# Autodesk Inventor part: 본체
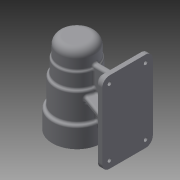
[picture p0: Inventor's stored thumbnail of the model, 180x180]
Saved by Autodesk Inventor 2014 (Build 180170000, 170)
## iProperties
Created: 2016-06
Part Number: 본체
Material: 일반
Document SubType Name: Modeling
Designer: SEC
Density: 1 g/cm^3
Appearance: 기본값
Mass: 247.993 g
Surface Area: 647.07 cm^2
Volume: 247.993 cm^3
Author: SEC
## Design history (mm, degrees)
sketch "스케치1"
  geometry: C1 r 34 at (0, 0); 1 further point
  constraints: 1 centre point, 1 coincident
  dimensions: "d0" = 68 diameter of C1
extrude "돌출1" new body sketch "스케치1" distance "d1" = 28; taper "d2" = 0 deg
sketch "스케치2"
  geometry: C1 r 34 at (0, 0) reference; C2 r 30 at (0, 0)
  constraints: 1 centre point, 1 coincident
  dimensions: "d3" = 60 diameter of C2
extrude "돌출2" join sketch "스케치2" distance "d4" = 39; taper "d5" = 0 deg
sketch "스케치3"
  geometry: C1 r 30 at (0, 0) reference; C2 r 27 at (0, 0)
  constraints: 1 centre point, 1 coincident
  dimensions: "d6" = 54 diameter of C2
extrude "돌출3" join sketch "스케치3" distance "d7" = 20; taper "d8" = 0 deg
sketch "스케치4"
  geometry: C1 r 27 at (0, 0) reference; C2 r 25 at (0, 0)
  constraints: 1 centre point, 1 coincident
  dimensions: "d9" = 50 diameter of C2
extrude "돌출4" join sketch "스케치4" distance "d10" = 25; taper "d11" = 0 deg
sketch "스케치5"
  geometry: L1 (-34, 0)-(-34, 28) reference; L2 (-34, 28)-(-30, 28) reference; L3 (-30, 28)-(-30, 67) reference; L4 (-30, 67)-(-27, 67) reference; L5 (-27, 67)-(-27, 87) reference; L6 (-27, 87)-(-25, 87) reference; L7 (-25, 87)-(-25, 112) reference; L8 (-25, 112)-(25, 112) reference; L9 (25, 112)-(25, 87) reference; L10 (25, 87)-(27, 87) reference; L11 (27, 87)-(27, 67) reference; L12 (27, 67)-(30, 67) reference; L13 (30, 67)-(30, 28) reference; L14 (30, 28)-(34, 28) reference; L15 (34, 28)-(34, 0) reference; L16 (34, 0)-(-34, 0) reference; L17 (-60, 112)-(-70, 112); L18 (-70, 112)-(-70, 0); L19 (-70, 0)-(-60, 0); L20 (-60, 0)-(-60, 112); L21 (0, 112)-(0, 0)
  constraints: 10 end point, 3 parallel, 1 collinear, 1 horizontal, 1 midpoint, 1 perpendicular
  dimensions: "d12" = 70 distance between parallel lines of L18 L21; "d13" = 10 distance between parallel lines of L18 L20; "d14" = 112 distance of L19.end L17.start; "d15" = 0 distance between parallel lines of L19 L16
extrude "돌출5" join sketch "스케치5" stored distance "d16" = 70; taper "d17" = 0 deg
node "작업 평면1"
sketch "스케치6"
  geometry: L1 (70, -35)-(60, -35) reference; L2 (60, -35)-(60, 35) reference; L3 (60, 35)-(70, 35) reference; L4 (70, 35)-(70, -35) reference; L5 (60, -28)-(15, -11.621); L6 (15, -11.621)-(15, 11.621); L7 (15, 11.621)-(60, 28); L8 (60, -28)-(60, 28); C1 r 30 at (0, 0) reference; 1 further point
  constraints: 8 end point, 2 point on line, 1 collinear, 1 parallel
  dimensions: "d18" = 110 deg angle of L2 L7; "d19" = 110 deg angle of L2 L5; "d20" = 7 distance from line of L7.end L3; "d21" = 7 distance from line of L1 L5.start; "d22" = 45 distance between parallel lines of L2 L6
extrude "돌출6" join sketch "스케치6" stored distance "d23" = 8; taper "d24" = 0 deg
node "작업 평면2"
sketch "스케치7"
  geometry: L1 (34, 0)-(34, -28) reference; L2 (34, -28)-(30, -28) reference; L3 (30, -28)-(30, -52) reference; L4 (30, -52)-(60, -52) reference; L5 (60, -52)-(60, 0) reference; L6 (60, 0)-(70, 0) reference; L7 (70, 0)-(70, -112) reference; L8 (70, -112)-(60, -112) reference; L9 (60, -112)-(60, -60) reference; L10 (60, -60)-(30, -60) reference; L11 (30, -60)-(30, -67) reference; L12 (30, -67)-(27, -67) reference; L13 (27, -67)-(27, -87) reference; L14 (27, -87)-(25, -87) reference; L15 (25, -87)-(25, -112) reference; L16 (25, -112)-(-25, -112) reference; L17 (-25, -112)-(-25, -87) reference; L18 (-25, -87)-(-27, -87) reference; L19 (-27, -87)-(-27, -67) reference; L20 (-27, -67)-(-30, -67) reference; L21 (-30, -67)-(-30, -28) reference; L22 (-30, -28)-(-34, -28) reference; L23 (-34, -28)-(-34, 0) reference; L24 (-34, 0)-(34, 0) reference; L25 (60, -92)-(20, -92); L26 (20, -92)-(20, -20); L27 (20, -20)-(60, -20); L28 (60, -20)-(60, -92); L29 (0, -112)-(0, 0)
  constraints: 10 end point, 3 parallel, 1 horizontal, 1 midpoint, 1 perpendicular, 1 point on line
  dimensions: "d25" = 20 distance between parallel lines of L8 L25; "d26" = 20 distance between parallel lines of L27 L6; "d27" = 40 distance between parallel lines of L9 L26
extrude "돌출7" join sketch "스케치7" stored distance "d28" = 8; taper "d29" = 0 deg
sketch "스케치8"
  geometry: L1 (-25, -112)-(-25, -87) reference; L2 (-25, -87)-(-27, -87) reference; L3 (-27, -87)-(-27, -67) reference; L4 (-27, -67)-(-30, -67) reference; L5 (-30, -67)-(-30, -28) reference; L6 (-30, -28)-(-34, -28) reference; L7 (-34, -28)-(-34, 0) reference; L8 (-34, 0)-(34, 0) reference; L9 (34, 0)-(34, -20) reference; L10 (34, -20)-(60, -20) reference; L11 (60, -20)-(60, 0) reference; L12 (60, 0)-(70, 0) reference; L13 (70, 0)-(70, -112) reference; L14 (70, -112)-(60, -112) reference; L15 (60, -112)-(60, -92) reference; L16 (60, -92)-(25, -92) reference; L17 (25, -92)-(25, -112) reference; L18 (25, -112)-(-25, -112) reference; L19 (0, 0)-(0, -112); L20 (-21, 0)-(-21, -15); L21 (-21, -15)-(-24, -15); L22 (-24, -15)-(-24, -69); L23 (-24, -69)-(-21, -69); L24 (-21, -69)-(-21, -81); L25 (-21, -81)-(-17.5, -81); L26 (-17.5, -81)-(-17.5, -99); L27 (-17.5, -99)-(-16, -99); L28 (-16, -99)-(-16, -103); L29 (-16, -103)-(-10.5, -103); L30 (-10.5, -103)-(-10.5, -106); L31 (-10.5, -106)-(0, -106)
  constraints: 26 end point, 10 parallel, 2 point on line, 1 collinear, 1 midpoint, 1 perpendicular
  dimensions: "d30" = 15 distance of L20.start L20.end; "d31" = 54 distance of L21.end L22.end; "d32" = 12 distance of L23.end L24.end; "d33" = 18 distance of L25.end L26.end; "d34" = 4 distance of L27.end L28.end; "d35" = 3 distance of L29.end L30.end; "d36" = 42 diameter of L20 L19; "d37" = 48 diameter of L22 L19; "d38" = 42 diameter of L24 L19; "d39" = 35 diameter of L26 L19; "d40" = 32 diameter of L28 L19; "d41" = 21 diameter of L30 L19
revolve "회전1" sketch "스케치8" stored, may be unused: angle "d42" = 90 deg
sketch "스케치9"
  geometry: L1 (0, 70)-(0, 0) reference; L2 (0, 0)-(-112, 0) reference; L3 (-10, 10)-(-102, 10); L4 (-102, 10)-(-102, 60); L5 (-102, 60)-(-10, 60); L6 (-10, 60)-(-10, 10); 5 further points
  constraints: 8 end point, 4 coincident, 2 parallel, 1 horizontal, 1 perpendicular
  dimensions: "d43" = 92 distance of L4.end L5.end; "d44" = 50 distance between parallel lines of L5 L3; "d45" = 10 distance between parallel lines of L1 L6; "d46" = 10 distance between parallel lines of L2 L3
hole "구멍1" sketch "스케치9" at (-10, 10), (-102, 10), (-102, 60), (-10, 60) diameter "d47" = 5; stored, may be unused: countersink angle "d51" = 90 deg, drill point angle "d53" = 118 deg; dims "d48" = 6, "d49" = 9, "d50" = 4, "d52" = 8
fillet "모깎기1" dims "d54" = 10
sketch "스케치10"
  geometry: C1 r 34 at (0, 0) reference; A1 r 26 centre (0, 0) between (26, 0) and (0, -26); 2 further points
  constraints: 4 point on circle, 1 centre point, 1 coincident
  dimensions: "d55" = 52 diameter of A1
hole "구멍2" sketch "스케치10" at (26, 0), (0, -26), (-26, 0), (0, 26) diameter "d56" = 3.242; stored, may be unused: countersink angle "d60" = 90 deg, drill point angle "d62" = 118 deg; dims "d57" = 8, "d58" = 9, "d59" = 4, "d61" = 11
node "작업 평면3"
sketch "스케치11"
  geometry: L1 (-34, -28)-(34, -28) reference; 3 further points
  constraints: 1 midpoint, 1 vertical alignment, 1 other
  dimensions: "d63" = 48 distance from line of point (0, 20) L1
feature "엠보싱1" sketch "스케치11" dims "d9" = 50, "d64" = 0.5, "d65" = 0
fillet "모깎기2" dims "d66" = 0.3
fillet "모깎기3" dims "d67" = 3
fillet "모깎기4" dims "d68" = 3
chamfer "모따기1" distance "d69" = 4; stored, may be unused: second distance "d70" = 2, angle "d71" = 45 deg
chamfer "모따기2" distance "d72" = 1; stored, may be unused: second distance "d73" = 2, angle "d74" = 45 deg
fillet "모깎기5" dims "d75" = 3
fillet "모깎기6" dims "d76" = 3
fillet "모깎기7" dims "d77" = 3
fillet "모깎기8" dims "d78" = 3
fillet "모깎기9" dims "d79" = 3
fillet "모깎기10" dims "d80" = 3
fillet "모깎기11" dims "d81" = 3
fillet "모깎기12" dims "d82" = 10
fillet "모깎기13" dims "d83" = 3
fillet "모깎기14" dims "d84" = 3
node "솔리드1"
node "절단 모서리 투영1"
node "절단 모서리 투영2"
node "절단 모서리 투영3"
node "절단 모서리 투영4"
